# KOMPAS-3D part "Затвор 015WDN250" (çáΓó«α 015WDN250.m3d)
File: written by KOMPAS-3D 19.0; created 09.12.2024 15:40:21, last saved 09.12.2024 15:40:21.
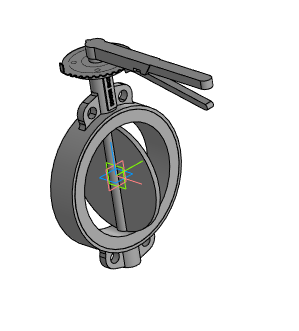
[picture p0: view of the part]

Document properties: Автор: Евгений; Полное имя файла: ..\Затвор 015WDN250.a3d

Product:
- Part/product: Затвор 015WDN250
    Масса: 29.5892

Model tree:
1. Операция без истории:1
